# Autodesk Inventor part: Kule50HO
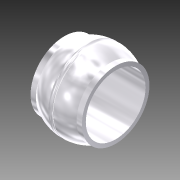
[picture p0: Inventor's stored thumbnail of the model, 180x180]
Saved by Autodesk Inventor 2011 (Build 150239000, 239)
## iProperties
Created: 2010-10
Part Number: Kule50HO
Document SubType Name: Modeling
Designer: tribel
Density: 1 g/cm^3
Author: tribel
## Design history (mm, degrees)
sketch "Sketch1"
  geometry: L1 (-30.1, 0)-(30.1, 0) reference; L2 (0, -6.935)-(0, 41.608) reference; L3 (-21.5, 28.25)-(-16.979, 28.25); L4 (-21.5, 28.25)-(-21.5, 0); L5 (-2, 0)-(-2, 32.899); L6 (-21.5, 25)-(-2, 25); L7 (21.5, 28.25)-(16.979, 28.25); L8 (21.5, 28.25)-(21.5, 0); L9 (21.5, 25)-(2, 25); L10 (2, 0)-(2, 32.899); L11 (-2, 25)-(2, 25); A1 r 2.674 centre (0, 34.674) between (-2, 32.899) and (2, 32.899); A2 r 32.96 centre (0, 0) between (16.979, 28.25) and (2, 32.899); A3 r 32.96 centre (0, 0) between (-2, 32.899) and (-16.979, 28.25)
  constraints: 18 end point, 7 symmetric about line, 6 point on circle, 6 point on line, 4 perpendicular, 3 centre point, 1 parallel
  dimensions: "d1" = 21.5 distance between parallel lines of L4 L2; "d2" = 2 distance between parallel lines of L5 L2; "d3" = 56.5 diameter of L3 L1; "d4" = 64 dimension on A1 L1; "d5" = 50 diameter of L9 L1; "d7" = 32.96 radius of A3
revolve "Revolution1" sketch "Sketch1" stored, may be unused: angle "d8" = 90 deg
body "Solid1"
other parameters: "d0" = 65.92, "d6" = 32.96
